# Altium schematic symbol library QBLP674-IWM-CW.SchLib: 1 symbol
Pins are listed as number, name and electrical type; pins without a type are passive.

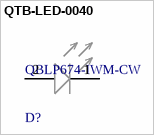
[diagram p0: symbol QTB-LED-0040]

## QTB-LED-0040
designator D?, comment QBLP674-IWM-CW
LED COOL WHITE 2PLCC SMD; Manufacturer: QT Brightek (QTB); Lens Size: 2.3mm; Luminous Intensity: 3400mcd; Lens Transparency: Diffused; Test Current: 30mA; Lens Color: Yellow; Lens Style: Oval with Flat Top; Forward Voltage: 3.2V; Viewing Angle: 120°
footprint QBLP674-IWM-CW
pins: 1 CATHODE (-), 2 ANODE (+)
